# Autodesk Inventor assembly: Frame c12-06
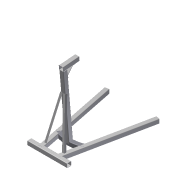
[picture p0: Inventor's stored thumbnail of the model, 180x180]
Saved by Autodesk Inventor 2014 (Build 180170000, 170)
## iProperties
Created: 2011-01
Part Number: Frame c12-06
Document SubType Name: Assembly
Designer: Thom Tremblay
Author: Thom Tremblay
_FrameDoc: Frame Assembly
_Version: 15.0.0
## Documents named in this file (20)
- C:\Inventor 2014 Essentials\Assemblies\Chapter 12\Frame\Frame c12-06.iam
- C:\Inventor 2014 Essentials\Assemblies\Chapter 12\Frame\Skeleton-c12-06.ipt
- C:\Inventor 2014 Essentials\Assemblies\Chapter 12\Frame\ANSI L 1.5 x 1.5 x 3_16 00000001.ipt
- ANSI L 1.5 x 1.5 x 3_16 00000001.ipt
- C:\Inventor 2014 Essentials\Assemblies\Chapter 12\Frame\ANSI L 1.5 x 1.5 x 3_16 00000002.ipt
- ANSI L 1.5 x 1.5 x 3_16 00000002.ipt
- C:\Inventor 2014 Essentials\Assemblies\Chapter 12\Frame\ANSI 3x3x3_16 00000025.ipt
- ANSI 3x3x3_16 00000025.ipt
- C:\Inventor 2014 Essentials\Assemblies\Chapter 12\Frame\ANSI 3x3x3_16 00000026.ipt
- ANSI 3x3x3_16 00000026.ipt
- C:\Inventor 2014 Essentials\Assemblies\Chapter 12\Frame\ANSI 3x3x3_16 00000027.ipt
- ANSI 3x3x3_16 00000027.ipt
- C:\Inventor 2014 Essentials\Assemblies\Chapter 12\Frame\ANSI 3x3x3_16 00000028.ipt
- ANSI 3x3x3_16 00000028.ipt
- C:\Inventor 2014 Essentials\Assemblies\Chapter 12\Frame\ANSI 3x3x3_16 00000029.ipt
- ANSI 3x3x3_16 00000029.ipt
- C:\Inventor 2014 Essentials\Assemblies\Chapter 12\Frame\ANSI 2 1_4x5_16 00000030.ipt
- ANSI 2 1_4x5_16 00000030.ipt
- C:\Inventor 2014 Essentials\Assemblies\Chapter 12\Frame\ANSI 3x3x3_16 00000059.ipt
- ANSI 3x3x3_16 00000059.ipt
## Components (10 placed, 10 different names)
1. Frame Reference Model
2. ANSI L 1.5 x 1.5 x 3_16 00000001:1
3. ANSI L 1.5 x 1.5 x 3_16 00000002:1
4. ANSI 3x3x3_16 00000025:1
5. ANSI 3x3x3_16 00000026:1
6. ANSI 3x3x3_16 00000027:1
7. ANSI 3x3x3_16 00000028:1
8. ANSI 3x3x3_16 00000029:1
9. ANSI 2 1_4x5_16 00000030:1
10. ANSI 3x3x3_16 00000059:1
